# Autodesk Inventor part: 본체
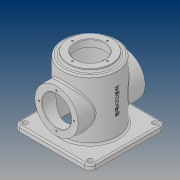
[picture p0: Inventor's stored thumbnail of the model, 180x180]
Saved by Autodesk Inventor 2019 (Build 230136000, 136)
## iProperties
Created: 2019-03
Part Number: 본체
Material: 일반
Document SubType Name: Modeling
Designer: PC312-02
Density: 1 g/cm^3
Appearance: 기본값
Author: PC312-02
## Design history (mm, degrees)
sketch "스케치1"
  geometry: C1 r 50 at (0, 0); 1 further point
  constraints: 1 centre point, 1 coincident
  dimensions: "d0" = 100 diameter of C1
extrude "돌출1" new body sketch "스케치1" distance "d1" = 120; taper "d2" = 0 deg
sketch "스케치2"
  geometry: C1 r 45 at (0, 0); 1 further point
  constraints: 1 centre point, 1 coincident
  dimensions: "d3" = 90 diameter of C1
extrude "돌출2" cut sketch "스케치2" distance "d4" = 112; taper "d5" = 0 deg
sketch "스케치3"
  geometry: L1 (70, 70)-(-70, 70); L2 (-70, 70)-(-70, -70); L3 (-70, -70)-(70, -70); L4 (70, -70)-(70, 70); L5 (70, 70)-(-70, -70); L6 (-70, 70)-(70, -70); C1 r 45 at (0, 0) reference; 1 further point
  constraints: 12 end point, 2 midpoint, 2 parallel, 1 horizontal, 1 perpendicular
  dimensions: "d6" = 140 distance of L3.end L2.end; "d7" = 140 distance of L2.end L1.end
extrude "돌출3" join sketch "스케치3" distance "d8" = 10; taper "d9" = 0 deg
node "작업 평면1"
sketch "스케치4"
  geometry: L1 (70, 0)-(-70, 0) reference; C1 r 40 at (0, 60); 2 further points
  constraints: 1 centre point, 1 midpoint, 1 vertical alignment
  dimensions: "d11" = 60 distance from line of L1 C1.centre; "d12" = 80 diameter of C1
extrude "돌출4" join sketch "스케치4" stored distance "d13" = 10; taper "d14" = 0 deg
sketch "스케치5"
  geometry: C1 r 40 at (0, 0); 1 further point
  constraints: 1 centre point, 1 coincident
  dimensions: "d15" = 80 diameter of C1
extrude "돌출5" join sketch "스케치5" distance "d16" = 5; taper "d17" = 0 deg
sketch "스케치6"
  geometry: C1 r 40 at (0, 0) reference; 2 further points
  constraints: 1 vertical alignment
  dimensions: "d18" = 32.5 distance of C1.centre point (0, 32.5)
hole "구멍1" sketch "스케치6" at (0, 32.5) diameter "d19" = 3.242; stored, may be unused: countersink angle "d23" = 90 deg, drill point angle "d25" = 118 deg; dims "d20" = 8, "d21" = 4, "d22" = 2, "d24" = 10
sketch "스케치7"
  geometry: 2 further points
  constraints: 1 vertical alignment
  dimensions: "d29" = 32.5 distance of point (0, 0) point (0, 32.5)
hole "구멍2" sketch "스케치7" at (0, 32.5) diameter "d30" = 3.242; stored, may be unused: countersink angle "d34" = 90 deg, drill point angle "d36" = 118 deg; dims "d31" = 8, "d32" = 4, "d33" = 2, "d35" = 10
sketch "스케치8"
  geometry: C1 r 40 at (0, 0) reference; C2 r 27 at (0, 0); 1 further point
  constraints: 1 centre point, 1 coincident
  dimensions: "d40" = 54 diameter of C2
extrude "돌출6" cut sketch "스케치8" extent not by distance; stored distance "d41" = 5; taper "d42" = 0 deg
sketch "스케치9"
  geometry: C1 r 27 at (0, 0); 1 further point
  constraints: 1 centre point, 1 coincident
  dimensions: "d43" = 54 diameter of C1
extrude "돌출7" cut sketch "스케치9" extent not by distance; stored distance "d44" = 5; taper "d45" = 0 deg
fillet "모깎기1" dims "d46" = 10
sketch "스케치10"
  geometry: A1 r 10 centre (-60, -60) between (-70, -60) and (-60, -70) reference; A2 r 10 centre (60, -60) between (60, -70) and (70, -60) reference; A3 r 10 centre (60, 60) between (70, 60) and (60, 70) reference; A4 r 10 centre (-60, 60) between (-60, 70) and (-70, 60) reference; 5 further points
  constraints: 4 coincident
hole "구멍3" sketch "스케치10" at (-60, -60), (60, -60), (60, 60), (-60, 60) diameter "d47" = 9; stored, may be unused: countersink angle "d51" = 90 deg, drill point angle "d53" = 118 deg; dims "d48" = 8, "d49" = 4, "d50" = 2, "d52" = 10
fillet "모깎기2" dims "d54" = 3
fillet "모깎기3" dims "d55" = 3
chamfer "모따기1" distance "d56" = 1; stored, may be unused: second distance "d57" = 2, angle "d58" = 45 deg
node "작업 평면2"
sketch "스케치11"
  geometry: L1 (0, -60)-(0, 60) reference; 3 further points
  constraints: 1 horizontal alignment, 1 midpoint, 1 other
  dimensions: "d60" = 70 distance from line of L1 point (70, 0)
feature "엠보싱1" sketch "스케치11" dims "d61" = 0.5, "d62" = 0
node "솔리드1"
pattern_circular "원형 패턴1" dims angle "d27" = 360 deg
mirror "미러1"
pattern_circular "원형 패턴2" dims angle "d38" = 360 deg
other parameters: "d10" = 62
